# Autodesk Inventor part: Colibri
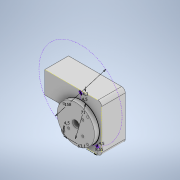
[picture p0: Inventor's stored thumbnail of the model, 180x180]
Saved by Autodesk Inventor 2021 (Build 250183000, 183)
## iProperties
Created: 2021-03
Part Number: Colibri
Material: Genérico
Document SubType Name: Modeling
Designer: ATOUZA
Density: 1 g/cm^3
Appearance: Valor por defecto
Author: ATOUZA
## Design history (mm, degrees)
sketch "Boceto1"
  geometry: L1 (-36.9, -38.8)-(40.1, -38.8); L2 (-67.9, 51.2)-(40.1, 51.2); L3 (40.1, 51.2)-(40.1, -38.8); L4 (-36.9, -38.8)-(-36.9, 4.4); L5 (-67.9, 51.2)-(-67.9, 9.2); L6 (-67.9, 9.2)-(-40.9, 9.2); L7 (-40.9, 9.2)-(-40.9, 4.4); L8 (-40.9, 4.4)-(-36.9, 4.4); C1 r 6.4 at (0, 0); C2 r 35.5 at (0, 0); 1 further point
  constraints: 16 end point, 3 perpendicular, 2 centre point, 2 coincident, 2 horizontal, 2 vertical, 1 parallel
  dimensions: "d0" = 12.8 diameter of C1; "d1" = 71 diameter of C2; "d2" = 38.8 distance from line of L1 C2.centre; "d3" = 90 distance between parallel lines of L2 L1; "d4" = 51.2 distance from line of L2 C2.centre (derived); "d5" = 40.1 distance from line of L3 C2.centre; "d6" = 77 distance of L1.start L1.end; "d7" = 108 distance of L2.start L2.end; "d8" = 42 distance of L2.start L5.end; "d9" = 27 distance of L5.end L6.end; "d10" = 4.8 distance of L6.end L7.end
extrude "Extrusión1" new body sketch "Boceto1" distance "d11" = 45; taper "d12" = 0 deg
fillet "Empalme1" dims "d13" = 7
sketch "Boceto2"
  geometry: L1 (33.1, 51.2)-(-67.9, 51.2) reference; L2 (0, 51.2)-(0, -38.8); L3 (-29.9, -38.8)-(33.1, -38.8) reference; L4 (40.1, -31.8)-(40.1, 44.2) reference; C1 r 6.4 at (0, 0) reference; C2 r 35.5 at (0, 0); C3 r 2.25 at (0, 46.9); C4 r 2.25 at (31.55, -25.526); C5 r 2.25 at (-31.55, -25.526); A1 r 79 centre (0, 46.9) between (31.55, -25.526) and (-31.55, -25.526); 3 further points
  constraints: 6 coincident, 5 centre point, 3 point on line, 2 end point, 2 point on circle, 1 vertical
  dimensions: "d14" = 71 diameter of C2; "d15" = 4.3 distance from line of point (0, 46.9) L1; "d16" = 158 diameter of A1; "d17" = 8.55 distance from line of A1.start L4; "d18" = 63.1 distance of A1.start A1.end; "d19" = 4.5 diameter of C3; "d20" = 4.5 diameter of C4; "d21" = 4.5 diameter of C5
extrude "Extrusión2" join sketch "Boceto2" distance "d22" = 9; taper "d23" = 0 deg
hole "Agujero1" sketch "Boceto2" diameter "d24" = 4.5; stored, may be unused: countersink angle "d28" = 90 deg, drill point angle "d30" = 118 deg; dims "d25" = 6, "d26" = 4, "d27" = 2, "d29" = 8
sketch "Boceto4"
  geometry: L1 (-22.5, -22.5)-(22.5, -22.5); L2 (22.5, -22.5)-(22.5, 22.5); L3 (22.5, 22.5)-(-22.5, 22.5); L4 (-22.5, 22.5)-(-22.5, -22.5); L5 (-22.5, -22.5)-(22.5, 22.5); L6 (22.5, -22.5)-(-22.5, 22.5); L7 (-13.5, -13.5)-(13.5, -13.5); L8 (13.5, -13.5)-(13.5, 13.5); L9 (13.5, 13.5)-(-13.5, 13.5); L10 (-13.5, 13.5)-(-13.5, -13.5); L11 (-13.5, -13.5)-(13.5, 13.5); L12 (13.5, -13.5)-(-13.5, 13.5); 8 further points
  constraints: 24 end point, 7 coincident, 4 midpoint, 4 parallel, 2 horizontal, 2 perpendicular
  dimensions: "d31" = 45 distance of L3.end L2.end; "d32" = 45 distance of L2.end L1.end; "d33" = 27 distance of L9.end L8.end; "d34" = 27 distance of L8.end L7.end
hole "Agujero2" sketch "Boceto4" at (13.5, 13.5), (22.5, 22.5), (-22.5, 22.5), (-13.5, -13.5), (13.5, -13.5), (22.5, -22.5), (-22.5, -22.5) diameter "d35" = 4; stored, may be unused: countersink angle "d39" = 90 deg, drill point angle "d41" = 118 deg; dims "d36" = 6, "d37" = 4, "d38" = 2, "d40" = 8
node "Sólido1"
